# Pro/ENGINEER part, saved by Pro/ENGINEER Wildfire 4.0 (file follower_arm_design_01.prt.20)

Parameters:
  METRIC = "NO"

Other parameters: PITCH, DRILL_DIAMETER, THREAD_DIAMETER, THREADS_PER_INCH, THREAD_DEPTH, THREAD_LENGTH, DRILL_POINT_ANGLE, DRILL_DEPTH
